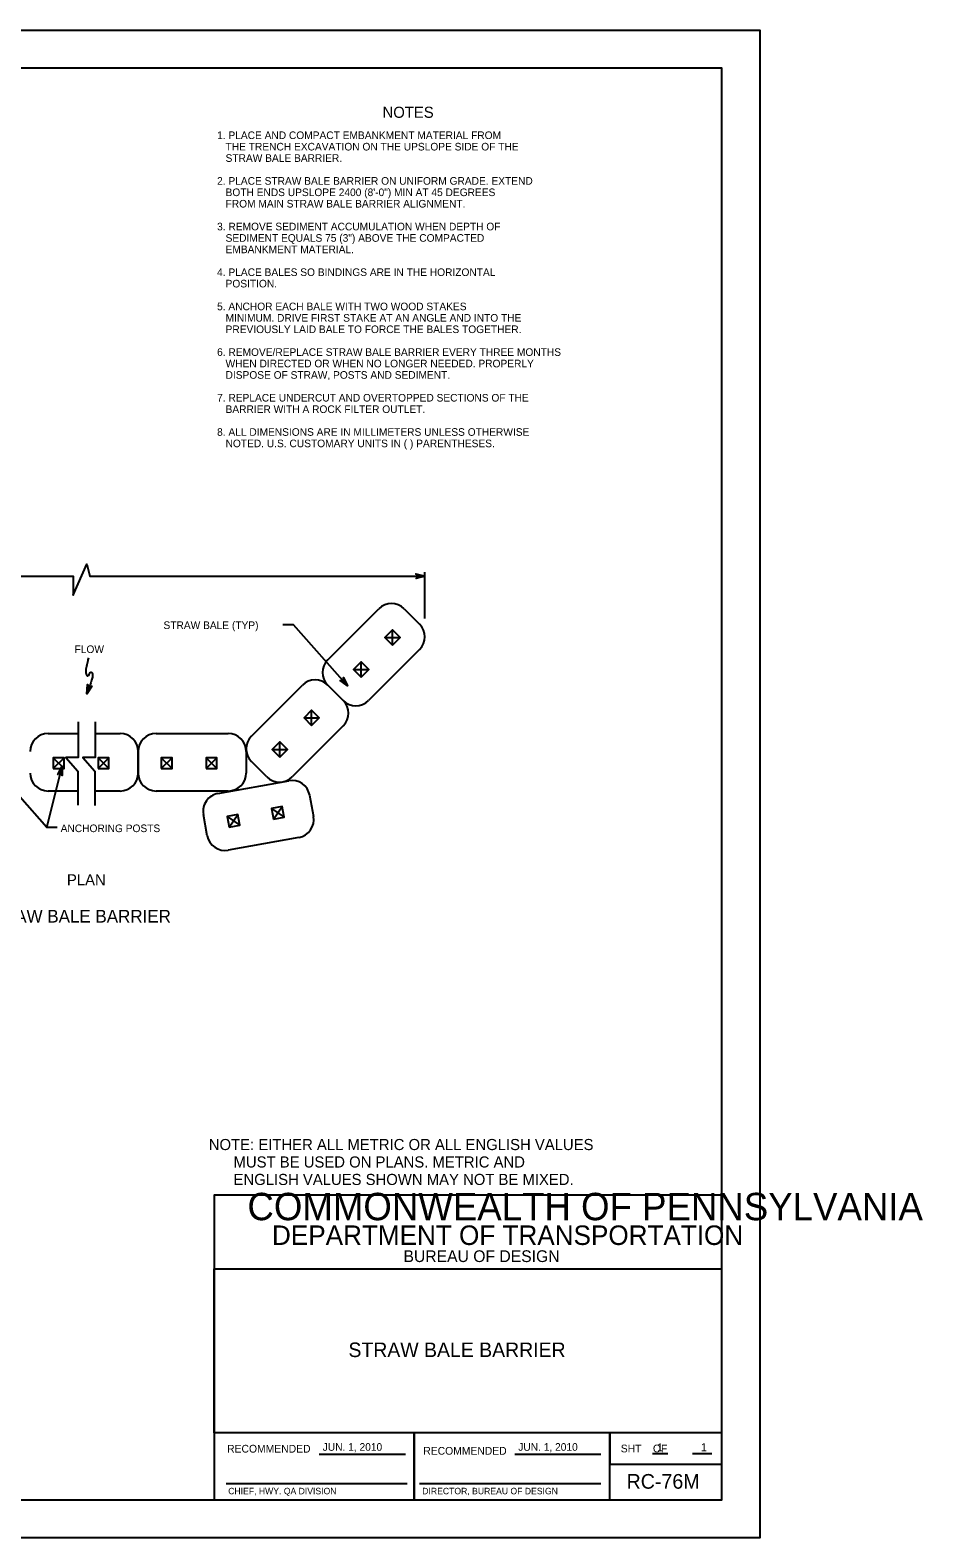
# Model space of a CAD drawing. Extents: x 636462 to 637367, y 299944 to 300538.
# Drawn here: x 637016 to 637367, y 299944 to 300538 of the extents above; entities that cross this region are included whole.
import ezdxf

# ---------------------------------------------------------------- set-up
doc = ezdxf.new("R2010")
doc.units = 0
for name, color, linetype in [('1', 7, 'Continuous'), ('2', 7, 'Continuous'), ('Default', 7, 'Continuous'), ('PLT-BNDY', 7, 'Continuous')]:
    doc.layers.add(name, color=color, linetype=linetype)

msp = doc.modelspace()

# ---------------------------------------------------------------- linework, layer by layer
at = {"layer": '1'}
for p, q in [((637129.38, 299977.44), (637163.27, 299977.44)), ((637206.38, 299977.44), (637240.25, 299977.44)), ((637260.54, 299977.66), (637266.68, 299977.66)), ((637276.35, 299977.66), (637283.99, 299977.66)), ((637092.68, 299965.87), (637163.93, 299965.87)), ((637168.85, 299965.87), (637240.19, 299965.87))]:
    msp.add_line(p, q, dxfattribs=at)
msp.add_lwpolyline([(637287.91, 299959.45), (637287.91, 300523.45), (636501.91, 300523.45), (636501.91, 299959.45), (637287.91, 299959.45), (637287.91, 299985.81), (637087.91, 299985.81), (637087.91, 300050.49), (637287.91, 300050.49), (637287.91, 300079.45), (637087.91, 300079.45), (637087.91, 299959.45), (637166.72, 299959.45), (637166.72, 299985.81), (637166.72, 299959.45), (637243.72, 299959.45), (637243.72, 299985.81), (637243.72, 299973.49), (637287.91, 299973.49)], dxfattribs=at)
at = {"layer": 'Default'}
for p, q in [((637170.95, 300306.59), (637170.95, 300324.88)), ((637155.22, 300299.14), (637161.23, 300299.2)), ((637158.25, 300296.16), (637158.19, 300302.18)), ((637142.85, 300286.51), (637148.86, 300286.57)), ((637145.89, 300283.53), (637145.82, 300289.55)), ((637123.35, 300267.49), (637129.36, 300267.49)), ((637126.35, 300264.48), (637126.35, 300270.5)), ((637113.86, 300251.99), (637113.86, 300258)), ((637024.62, 300251.81), (637028.87, 300247.56)), ((637024.62, 300247.56), (637028.87, 300251.81)), ((637042.3, 300251.81), (637046.55, 300247.56)), ((637042.3, 300247.56), (637046.55, 300251.81)), ((637067.14, 300251.81), (637071.39, 300247.56)), ((637067.14, 300247.56), (637071.39, 300251.81)), ((637084.82, 300251.81), (637089.07, 300247.56)), ((637084.82, 300247.56), (637089.07, 300251.81)), ((637110.85, 300254.99), (637116.86, 300254.99)), ((637110.53, 300231.79), (637115.47, 300228.36)), ((637111.28, 300227.6), (637114.71, 300232.54)), ((637093.14, 300228.65), (637098.08, 300225.22)), ((637093.89, 300224.46), (637097.32, 300229.4))]:
    msp.add_line(p, q, dxfattribs=at)
for points in [[(636902.92, 300323.36), (637032.4, 300323.36), (637032.4, 300315.78), (637037.86, 300328.03), (637039, 300323.3), (637170.95, 300323.35)], [(637167.72, 300323.99), (637167.45, 300324.22), (637170.95, 300323.35), (637167.72, 300323.99), (637167.92, 300323.62), (637170.95, 300323.35), (637167.92, 300323.1), (637167.74, 300322.72), (637170.95, 300323.35), (637167.46, 300322.47), (637167.74, 300322.72)], [(637132.72, 300290.39), (637152.77, 300310.43)], [(637162.79, 300310.43), (637168.8, 300304.42)], [(637115.02, 300304.27), (637119.05, 300304.27), (637140.54, 300280.19)], [(637168.8, 300294.4), (637148.76, 300274.35)], [(637039.49, 300279.84), (637039.79, 300280.03), (637037.83, 300276.99), (637039.49, 300279.84), (637039.07, 300279.78), (637037.83, 300276.99), (637038.57, 300279.94), (637038.28, 300280.24), (637037.83, 300276.99), (637038.13, 300280.59), (637038.28, 300280.24)], [(637102.66, 300260.32), (637122.7, 300280.37)], [(637132.72, 300280.37), (637138.74, 300274.35)], [(637138.74, 300274.35), (637132.72, 300280.37)], [(637138.86, 300283.03), (637138.84, 300283.38), (637140.54, 300280.19), (637138.86, 300283.03), (637138.71, 300282.63), (637140.54, 300280.19), (637138.32, 300282.28), (637137.92, 300282.16), (637140.54, 300280.19), (637137.54, 300282.2), (637137.92, 300282.16)], [(637022.6, 300261.37), (637034.38, 300261.37)], [(637034.38, 300266), (637034.38, 300251.93), (637029.58, 300251.93), (637034.31, 300246.47), (637034.31, 300233.14)], [(637041.05, 300266), (637041.05, 300251.93), (637036.25, 300251.93), (637040.97, 300246.47), (637040.97, 300232.98)], [(637041.05, 300261.37), (637050.95, 300261.37)], [(637065.12, 300261.37), (637093.47, 300261.37)], [(637138.74, 300264.33), (637118.69, 300244.29)], [(637058.03, 300245.78), (637058.03, 300254.28)], [(637058.03, 300254.28), (637058.03, 300245.78)], [(637100.55, 300254.28), (637100.55, 300245.78)], [(637108.67, 300244.29), (637102.66, 300250.3)], [(637026.15, 300224.35), (637022.12, 300224.35), (637000.63, 300248.42)], [(637026.15, 300224.35), (637022.12, 300224.35), (637028.09, 300248.42)], [(637026.72, 300245.42), (637026.44, 300245.21), (637028.09, 300248.42), (637026.72, 300245.42), (637027.13, 300245.53), (637028.09, 300248.42), (637027.64, 300245.41), (637027.96, 300245.15), (637028.09, 300248.42), (637028.15, 300244.82), (637027.96, 300245.15)], [(637034.31, 300238.69), (637022.6, 300238.69)], [(637050.95, 300238.69), (637040.97, 300238.69)], [(637093.47, 300238.69), (637065.12, 300238.69)], [(637089.45, 300237.7), (637117.34, 300242.73)], [(637125.57, 300237.02), (637127.09, 300228.65)], [(637085.24, 300221.09), (637083.73, 300229.46)], [(637121.37, 300220.42), (637093.48, 300215.38)]]:
    msp.add_lwpolyline(points, dxfattribs=at)
for points in [[(637158.25, 300296.16), (637161.23, 300299.2), (637158.19, 300302.18), (637155.22, 300299.14)], [(637145.89, 300283.53), (637148.86, 300286.57), (637145.82, 300289.55), (637142.85, 300286.51)], [(637126.35, 300264.48), (637129.36, 300267.49), (637126.35, 300270.5), (637123.35, 300267.49)], [(637113.86, 300251.99), (637116.86, 300254.99), (637113.86, 300258), (637110.85, 300254.99)], [(637024.62, 300247.56), (637028.87, 300247.56), (637028.87, 300251.81), (637024.62, 300251.81)], [(637042.3, 300247.56), (637046.55, 300247.56), (637046.55, 300251.81), (637042.3, 300251.81)], [(637067.14, 300247.56), (637071.39, 300247.56), (637071.39, 300251.81), (637067.14, 300251.81)], [(637084.82, 300247.56), (637089.07, 300247.56), (637089.07, 300251.81), (637084.82, 300251.81)], [(637111.28, 300227.6), (637115.47, 300228.36), (637114.71, 300232.54), (637110.53, 300231.79)], [(637093.89, 300224.46), (637098.08, 300225.22), (637097.32, 300229.4), (637093.14, 300228.65)]]:
    msp.add_lwpolyline(points, close=True, dxfattribs=at)
for centre, start, end in [((637157.78, 300305.42), 44.99996, 134.99996), ((637163.79, 300299.41), 314.99996, 44.99996), ((637137.74, 300285.38), 134.99996, 224.99996), ((637127.71, 300275.35), 44.99996, 134.99996), ((637133.73, 300269.34), 314.99996, 44.99996), ((637143.75, 300279.36), 224.99996, 314.99996), ((637022.6, 300254.28), 90, 180), ((637050.95, 300254.28), 360, 90), ((637065.12, 300254.28), 90, 180), ((637093.47, 300254.28), 360, 90), ((637107.67, 300255.31), 134.99996, 224.99996), ((637022.6, 300245.78), 180, 270), ((637050.95, 300245.78), 270, 0), ((637065.12, 300245.78), 180, 270), ((637093.47, 300245.78), 270, 0), ((637113.68, 300249.3), 224.99996, 314.99996), ((637090.71, 300230.72), 100.23688, 190.23688), ((637118.6, 300235.76), 10.23688, 100.23688), ((637120.11, 300227.39), 280.23688, 10.23688), ((637092.22, 300222.35), 190.23688, 280.23688)]:
    msp.add_arc(centre, 7.09, start, end, dxfattribs=at)
msp.add_spline([(637038.47, 300291.22), (637038.07, 300289.47), (637037.6, 300287.25), (637037.6, 300284.7), (637038.15, 300283.99), (637038.79, 300284.62), (637039.18, 300285.42), (637039.58, 300285.5), (637040.06, 300284.47), (637039.82, 300282.8), (637039.26, 300280.89), (637038.55, 300279.06), (637037.83, 300276.99)], degree=3, dxfattribs=at)
at = {"layer": 'PLT-BNDY'}
msp.add_lwpolyline([(636461.91, 300538.45), (637302.91, 300538.45), (637302.91, 299944.45), (636461.91, 299944.45)], close=True, dxfattribs=at)

# ---------------------------------------------------------------- texts
at = {"layer": '1'}
for s, height, p in [('COMMONWEALTH OF PENNSYLVANIA', 10.7834, (637101.07, 300069.59)), ('DEPARTMENT OF TRANSPORTATION', 7.6843, (637110.75, 300059.84)), ('BUREAU OF DESIGN', 4.6221, (637162.52, 300053.11)), ('RECOMMENDED', 3.048, (637093.08, 299978.04)), ('JUN. 1, 2010', 3, (637130.72, 299978.76)), ('APPROVED', 0.0192, (637130.94, 299977.38)), ('APPROVED', 0.0192, (637130.94, 299977.38)), ('APPROVED', 0.0192, (637130.94, 299977.38)), ('APPROVED', 0.0192, (637130.94, 299977.38)), ('RECOMMENDED', 3.048, (637170.32, 299977.21)), ('JUN. 1, 2010', 3, (637207.72, 299978.76)), ('SHT    OF', 3.048, (637248.08, 299978.12)), ('1', 3.13, (637262.41, 299978.54)), ('1', 3.13, (637279.64, 299978.59)), ('CHIEF, HWY. QA DIVISION', 2.54, (637093.5, 299961.62)), ('DIRECTOR, BUREAU OF DESIGN', 2.54, (637169.92, 299961.62))]:
    msp.add_text(s, height=height, dxfattribs=at).set_placement(p)
at = {"layer": '2'}
for s, p in [('NOTE: EITHER ALL METRIC OR ALL ENGLISH VALUES', (637085.85, 300097.22)), ('      MUST BE USED ON PLANS. METRIC AND', (637085.85, 300090.35)), ('      ENGLISH VALUES SHOWN MAY NOT BE MIXED.', (637085.85, 300083.47))]:
    msp.add_text(s, height=4.375, dxfattribs=at).set_placement(p)
at = {"layer": 'Default'}
for s, height, p in [('NOTES', 4.372, (637154.28, 300503.91)), ('1. PLACE AND COMPACT EMBANKMENT MATERIAL FROM', 2.998, (637089.12, 300495.55)), ('   THE TRENCH EXCAVATION ON THE UPSLOPE SIDE OF THE', 2.998, (637089.12, 300491.05)), ('   STRAW BALE BARRIER.', 2.998, (637089.12, 300486.56)), ('2. PLACE STRAW BALE BARRIER ON UNIFORM GRADE. EXTEND ', 2.998, (637089.12, 300477.56)), ('   BOTH ENDS UPSLOPE 2400 (8\'-0") MIN AT 45 DEGREES', 2.998, (637089.12, 300473.07)), ('   FROM MAIN STRAW BALE BARRIER ALIGNMENT.', 2.998, (637089.12, 300468.57)), ('3. REMOVE SEDIMENT ACCUMULATION WHEN DEPTH OF ', 2.998, (637089.12, 300459.58)), ('   SEDIMENT EQUALS 75 (3") ABOVE THE COMPACTED', 2.998, (637089.12, 300455.08)), ('   EMBANKMENT MATERIAL.', 2.998, (637089.12, 300450.58)), ('4. PLACE BALES SO BINDINGS ARE IN THE HORIZONTAL ', 2.998, (637089.12, 300441.59)), ('   POSITION.', 2.998, (637089.12, 300437.09)), ('5. ANCHOR EACH BALE WITH TWO WOOD STAKES ', 2.998, (637089.12, 300428.1)), ('   MINIMUM. DRIVE FIRST STAKE AT AN ANGLE AND INTO THE ', 2.998, (637089.12, 300423.6)), ('   PREVIOUSLY LAID BALE TO FORCE THE BALES TOGETHER.', 2.998, (637089.12, 300419.1)), ('6. REMOVE/REPLACE STRAW BALE BARRIER EVERY THREE MONTHS', 2.998, (637089.12, 300410.11)), ('   WHEN DIRECTED OR WHEN NO LONGER NEEDED. PROPERLY', 2.998, (637089.12, 300405.61)), ('   DISPOSE OF STRAW, POSTS AND SEDIMENT.', 2.998, (637089.12, 300401.11)), ('7. REPLACE UNDERCUT AND OVERTOPPED SECTIONS OF THE', 2.998, (637089.12, 300392.12)), ('   BARRIER WITH A ROCK FILTER OUTLET.', 2.998, (637089.12, 300387.62)), ('8. ALL DIMENSIONS ARE IN MILLIMETERS UNLESS OTHERWISE ', 2.998, (637089.12, 300378.63)), ('   NOTED. U.S. CUSTOMARY UNITS IN ( ) PARENTHESES.', 2.998, (637089.12, 300374.13)), ('STRAW BALE (TYP)', 2.998, (637068.01, 300302.51)), ('FLOW', 2.998, (637033, 300293.05)), ('ANCHORING POSTS', 2.998, (637027.52, 300222.49)), ('PLAN', 4.372, (637029.99, 300201.51)), ('STRAW BALE BARRIER', 4.9967, (636996.29, 300186.86)), ('STRAW BALE BARRIER', 5.7257, (637140.85, 300015.67)), ('RC-76M', 5.779, (637250.37, 299963.81))]:
    msp.add_text(s, height=height, dxfattribs=at).set_placement(p)

doc.saveas('drawing.dxf')
